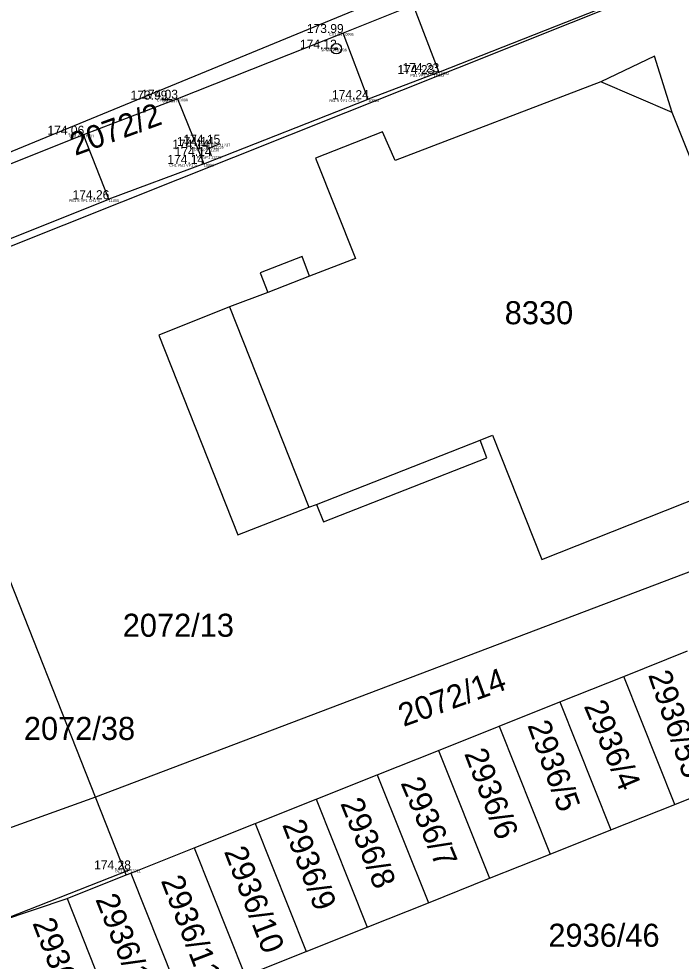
# Model space of a CAD drawing. Extents: x -566117 to -565580, y -1202428 to -1201938.
# Drawn here: x -565650.99 to -565619.32, y -1202198.94 to -1202153.92 of the extents above; entities that cross this region are included whole.
import ezdxf

# ---------------------------------------------------------------- set-up
doc = ezdxf.new("R2010")
doc.units = 0
for name, color, linetype in [('(Construction)', 7, 'Continuous'), ('_0', 7, 'Continuous'), ('Bod', 7, 'Continuous'), ('Implicitní', 7, 'Continuous'), ('Kanalizace', 7, 'Continuous'), ('Katastr', 7, 'Continuous'), ('Kod', 7, 'Continuous'), ('Oplocení', 7, 'Continuous'), ('Vrstva 61', 7, 'Continuous'), ('Výška', 7, 'Continuous'), ('Zpevněné plohy', 7, 'Continuous'), ('Číslo', 7, 'Continuous')]:
    doc.layers.add(name, color=color, linetype=linetype)

# ---------------------------------------------------------------- blocks, each defined once
blk = doc.blocks.new('A$C69D74C1E')
at = {"layer": 'Katastr'}
for p, q in [((445.18, -89.96), (441.77, -88.49)), ((427.84, -97.78), (425.84, -98.55)), ((424.02, -99.24), (427.8, -108.81)), ((428.18, -108.68), (436, -105.61)), ((455.52, -108.29), (417.61, -122.66)), ((442.86, -116.9), (445.91, -115.68)), ((439.81, -118.11), (442.86, -116.9)), ((445.3, -123.01), (442.86, -116.9)), ((436.91, -119.27), (439.81, -118.11)), ((439.81, -118.11), (442.25, -124.23)), ((434.01, -120.43), (436.91, -119.27)), ((436.91, -119.27), (439.35, -125.39)), ((431.08, -121.6), (434.01, -120.43)), ((434.01, -120.43), (436.45, -126.54)), ((428.15, -122.76), (431.08, -121.6)), ((431.08, -121.6), (433.52, -127.71)), ((445.3, -123.01), (448.35, -121.8)), ((419.08, -126.38), (417.61, -122.66)), ((425.24, -123.92), (428.15, -122.76)), ((428.15, -122.76), (430.59, -128.88)), ((442.25, -124.23), (445.3, -123.01)), ((422.33, -125.08), (425.24, -123.92)), ((425.24, -123.92), (427.68, -130.04)), ((439.35, -125.39), (442.25, -124.23)), ((419.29, -126.3), (422.33, -125.08)), ((422.33, -125.08), (424.77, -131.2)), ((436.45, -126.54), (439.35, -125.39)), ((416.25, -127.51), (419.08, -126.38)), ((419.08, -126.38), (419.29, -126.3)), ((419.29, -126.3), (421.73, -132.41)), ((433.52, -127.71), (436.45, -126.54)), ((413.08, -128.57), (416.25, -127.51)), ((416.25, -127.51), (418.69, -133.63)), ((430.59, -128.88), (433.52, -127.71)), ((427.68, -130.04), (430.59, -128.88)), ((424.77, -131.2), (427.68, -130.04))]:
    blk.add_line(p, q, dxfattribs=at)
for points in [[(397.89, -99.83), (397.46, -98.45), (446.91, -78.1)], [(417.61, -122.66), (408.07, -98.53), (445.72, -83.51), (455.52, -108.29)], [(430.04, -96.93), (427.84, -97.78), (427.49, -96.84), (425.48, -97.61), (425.84, -98.55), (424.02, -99.24), (420.64, -100.6), (424.41, -110.14), (427.8, -108.81), (428.18, -108.68), (428.5, -109.51), (436.32, -106.45), (436, -105.61), (436.58, -105.38), (438.94, -111.32), (451.69, -106.26), (445.18, -89.96), (444.33, -87.26), (441.77, -88.49), (431.93, -92.25), (431.32, -90.88), (428.13, -92.14), (430.04, -96.93)], [(417.61, -122.66), (406.22, -126.76), (405.4, -124.11)]]:
    blk.add_lwpolyline(points, dxfattribs=at)
for s, rotation, p in [('2072/2', 20, (416.635, -92.035)), ('2072/14', 20, (432.335, -119.315)), ('2936/55', 289, (444.017, -116.821)), ('2936/4', 293, (440.938, -118.307)), ('2936/5', 290, (438.245, -119.225)), ('2936/6', 291, (435.222, -120.579)), ('2936/7', 293, (432.178, -121.987)), ('2936/8', 292, (429.3, -122.963)), ('2936/9', 291, (426.522, -123.979)), ('2936/10', 291, (423.742, -125.259)), ('2936/11', 291, (420.722, -126.649)), ('2936/12', 292, (417.59, -127.543)), ('2936/13', 291, (414.582, -128.679))]:
    blk.add_text(s, height=1.1, rotation=rotation, dxfattribs=at).set_placement(p)
for s, p in [('8330', (437.17, -100.073)), ('2072/13', (418.91, -115.003)), ('2072/38', (414.185, -119.933)), ('2936/46', (439.257, -129.813))]:
    blk.add_text(s, height=1.1, dxfattribs=at).set_placement(p)
blk = doc.blocks.new('SPMR')
at = {"layer": '_0'}
for radius in [0.25, 0.05]:
    blk.add_circle((0, 0), radius, dxfattribs=at)
blk = doc.blocks.new('VP')
at = {"layer": 'Kanalizace'}
blk.add_line((-0.25, 0), (0.25, 0), dxfattribs=at)
blk = doc.blocks.new('POINT_DISPLAY')
at = {"layer": 'Implicitní'}
blk.add_line((0, 0), (0, 0), dxfattribs=at)

msp = doc.modelspace()

# ---------------------------------------------------------------- linework, layer by layer
at = {"layer": '(Construction)'}
msp.add_line((-565655.28, -1202198.35), (-565645.65, -1202194.56), dxfattribs=at)
at = {"layer": '_0'}
for p, q in [((-565641.38, -1202159.89), (-565641.91, -1202160.12)), ((-565641.91, -1202160.12), (-565641.8, -1202160.47))]:
    msp.add_line(p, q, dxfattribs=at)
at = {"layer": 'Oplocení'}
for p, q in [((-565631.15, -1202156.56), (-565634.28, -1202157.76)), ((-565642.15, -1202160.85), (-565634.28, -1202157.76)), ((-565642.15, -1202160.85), (-565646.69, -1202162.54))]:
    msp.add_line(p, q, dxfattribs=at)
for points in [[(-565631.15, -1202156.56), (-565630.91, -1202156.47), (-565619.21, -1202151.85), (-565615.22, -1202162.06)], [(-565655.4, -1202170.47), (-565656.72, -1202166.55), (-565646.69, -1202162.54)]]:
    msp.add_lwpolyline(points, dxfattribs=at)
at = {"layer": 'Zpevněné plohy'}
for p, q in [((-565632.14, -1202153.27), (-565635.48, -1202154.6)), ((-565632.14, -1202153.27), (-565630.91, -1202156.47)), ((-565635.48, -1202154.6), (-565643.4, -1202157.74)), ((-565634.28, -1202157.76), (-565635.48, -1202154.6)), ((-565643.4, -1202157.74), (-565647.89, -1202159.46)), ((-565643.4, -1202157.74), (-565642.15, -1202160.85)), ((-565647.89, -1202159.46), (-565652.68, -1202161.37)), ((-565646.69, -1202162.54), (-565647.89, -1202159.46))]:
    msp.add_line(p, q, dxfattribs=at)

# ---------------------------------------------------------------- block references
at = {"layer": '_0'}
msp.add_blockref('SPMR', (-565635.81, -1202155.35), dxfattribs=at)
at = {"layer": 'Bod'}
for p in [(-565635.48, -1202154.6), (-565635.81, -1202155.35), (-565631.15, -1202156.56), (-565630.91, -1202156.47), (-565643.91, -1202157.78), (-565643.4, -1202157.74), (-565634.28, -1202157.76), (-565647.89, -1202159.46), (-565641.91, -1202160.12), (-565641.69, -1202159.99), (-565641.38, -1202159.89), (-565641.8, -1202160.47), (-565642.15, -1202160.85), (-565646.69, -1202162.54), (-565645.65, -1202194.56)]:
    msp.add_blockref('POINT_DISPLAY', p, dxfattribs=at)
at = {"layer": 'Implicitní'}
msp.add_blockref('A$C69D74C1E', (-566064.93, -1202068.44), dxfattribs=at)
at = {"layer": 'Vrstva 61'}
msp.add_blockref('VP', (-565643.91, -1202157.78), dxfattribs=at)

# ---------------------------------------------------------------- texts
at = {"layer": 'Kod'}
for s, p in [('CH1 C1', (-565636.162, -1202154.73)), ('SPMR W', (-565636.554, -1202155.48)), ('PB1 VP1 S', (-565632.272, -1202156.69)), ('CH1 PB1', (-565631.722, -1202156.6)), ('C1 CH1 S', (-565644.392, -1202157.87)), ('UV', (-565644.127, -1202157.91)), ('PB1 S VP1 CH1 S', (-565636.182, -1202157.89)), ('CH1 C1', (-565648.572, -1202159.59)), ('PRISP1', (-565642.592, -1202160.25)), ('PRISP1 S', (-565642.372, -1202160.02)), ('HUP', (-565642.031, -1202160.12)), ('PRISP1', (-565642.482, -1202160.6)), ('CH1 PB1 VP1 S', (-565643.792, -1202160.98)), ('PB1 S VP1 CH1 S', (-565648.592, -1202162.67)), ('BZ1 PK', (-565646.375, -1202194.69))]:
    msp.add_text(s, height=0.13, dxfattribs=at).set_placement(p)
at = {"layer": 'Výška'}
for s, p in [('173.99 ', (-565637.217, -1202154.6)), ('174.12 ', (-565637.547, -1202155.35)), ('174.23 ', (-565632.887, -1202156.56)), ('174.23 ', (-565632.647, -1202156.47)), ('173.99 ', (-565645.647, -1202157.78)), ('174.03 ', (-565645.137, -1202157.74)), ('174.24 ', (-565636.017, -1202157.76)), ('174.06 ', (-565649.618, -1202159.46)), ('174.14 ', (-565643.647, -1202160.12)), ('174.14 ', (-565643.427, -1202159.99)), ('174.15 ', (-565643.117, -1202159.89)), ('174.14 ', (-565643.537, -1202160.47)), ('174.14 ', (-565643.887, -1202160.85)), ('174.26 ', (-565648.418, -1202162.54)), ('174.28 ', (-565647.387, -1202194.56))]:
    msp.add_text(s, height=0.43, dxfattribs=at).set_placement(p)
at = {"layer": 'Číslo'}
for s, p in [('10995', (-565635.48, -1202154.73)), ('10996', (-565635.81, -1202155.48)), ('10993', (-565631.15, -1202156.69)), ('10992', (-565630.91, -1202156.6)), ('10997', (-565643.91, -1202157.91)), ('10998', (-565643.4, -1202157.87)), ('10994', (-565634.28, -1202157.89)), ('11001', (-565647.89, -1202159.59)), ('11238', (-565641.91, -1202160.25)), ('11236', (-565641.69, -1202160.12)), ('11237', (-565641.38, -1202160.02)), ('11239', (-565641.8, -1202160.6)), ('10999', (-565642.15, -1202160.98)), ('11000', (-565646.69, -1202162.67)), ('13311', (-565645.65, -1202194.69))]:
    msp.add_text(s, height=0.13, dxfattribs=at).set_placement(p)

doc.saveas('drawing.dxf')
